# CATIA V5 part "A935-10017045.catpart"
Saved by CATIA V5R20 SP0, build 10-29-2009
Part number: A935-10017045
Source: Unknown
Property "A": "60.000"
Property "ARTICLENO": "A935-10017045"
Property "B": "20.000"
Property "BOMINFO": "A935-10017045"
Property "CODE": "A935-10017045"
Property "L": "170.000"
Property "L1": "143.370"
Property "LINA": "A935-10017045"
Property "NB": "A935-10017045"
Property "NBSYN": "$CODE."
Property "NN": "A935"
Property "NT": "VDI 3357 H-Type Cam Drivers, steel (16MnCr5)"
Property "SUPPLIER": "CF"
Property "T": "45.000"
Property "W": "100.000"
Bounding box of the stored display mesh (mm): x 0 to 170, y 0 to 45, z -100 to 0
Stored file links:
  C:\Users\Utente\Desktop\3D files A935\A935-10017045.catpart
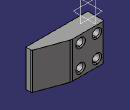
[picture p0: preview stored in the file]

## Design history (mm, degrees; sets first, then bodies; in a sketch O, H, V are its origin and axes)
Body1 "Geometry.1" (main body)
  Solid1 "A935-10017045.catpart": solid without history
